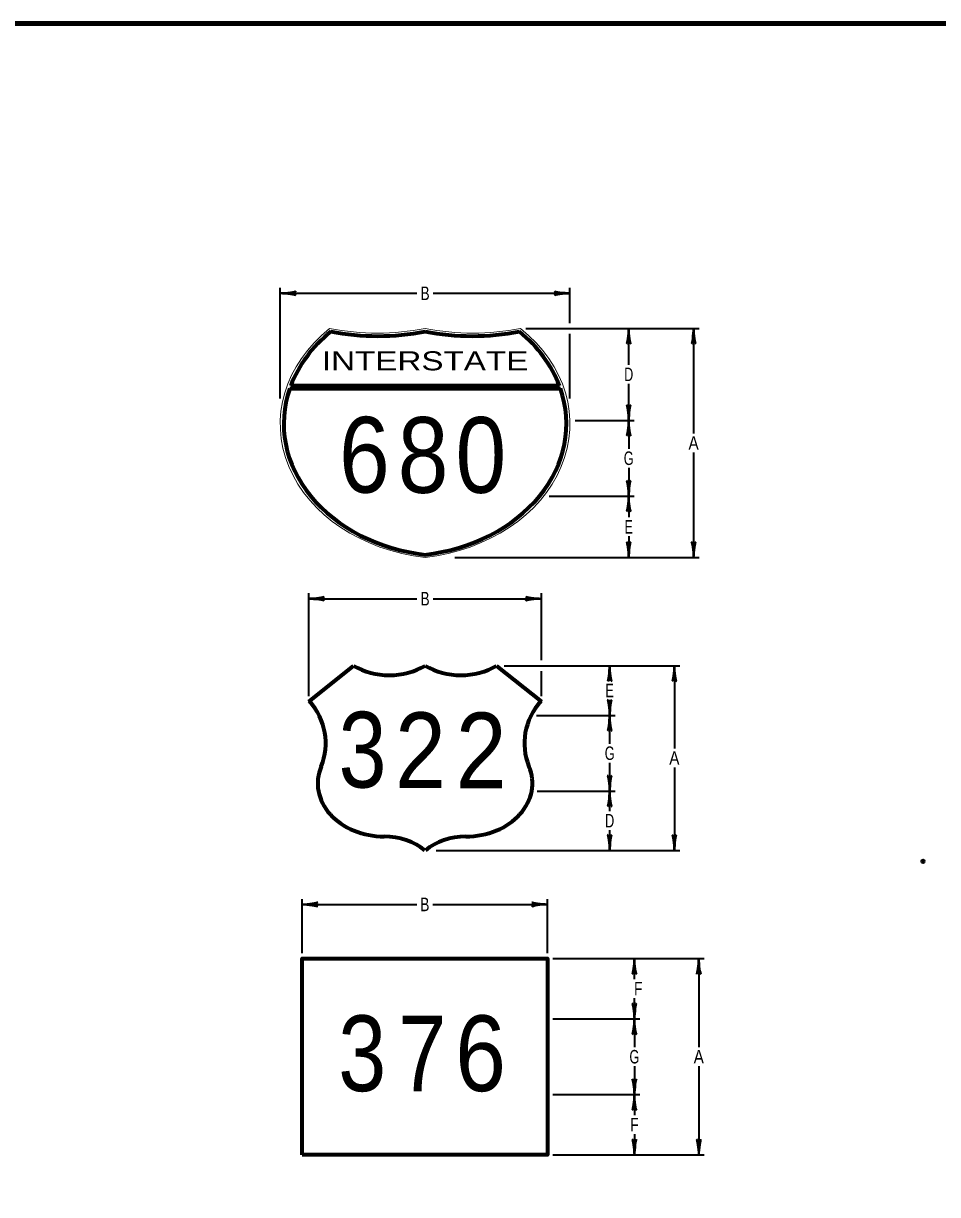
# Model space of a CAD drawing. Extents: x -96 to 760, y -448 to 96.
# Drawn here: x 135.6 to 338.4, y -170.2 to 89.7 of the extents above; entities that cross this region are included whole.
import ezdxf
from ezdxf.enums import TextEntityAlignment as Align

# ---------------------------------------------------------------- set-up
doc = ezdxf.new("R2010")
doc.units = 0
doc.header["$LTSCALE"] = 1.4
doc.header["$PDMODE"] = 32
doc.header["$PDSIZE"] = 0.7
doc.layers.add('1', color=7, linetype='Continuous', lineweight=40)

msp = doc.modelspace()

# ---------------------------------------------------------------- linework, layer by layer
at = {"layer": '1', "lineweight": 35}
for p, q in [((192.539, 6.466), (192.539, 30.981)), ((192.539, 29.781), (222.877, 29.781)), ((226.477, 29.781), (256.815, 29.781)), ((256.815, 23.192), (256.815, 30.981)), ((247.053, 21.992), (285.453, 21.992)), ((256.815, 6.466), (256.815, 20.792)), ((269.853, 13.892), (269.853, 21.992)), ((284.253, 21.992), (284.253, -1.319)), ((269.853, 1.592), (269.853, 9.692)), ((258.005, 1.592), (271.053, 1.592)), ((269.853, 1.592), (269.853, -4.708)), ((284.253, -5.519), (284.253, -28.831)), ((252.208, -15.208), (271.053, -15.208)), ((269.853, -24.119), (269.853, -28.831)), ((231.312, -28.831), (285.453, -28.831)), ((198.87, -59.569), (198.87, -36.769)), ((198.87, -37.969), (222.877, -37.969)), ((226.477, -37.969), (250.484, -37.969)), ((250.484, -51.629), (250.484, -36.769)), ((242.195, -52.829), (281.182, -52.829)), ((250.484, -59.569), (250.484, -54.029)), ((265.63, -56.239), (265.63, -52.829)), ((279.982, -52.829), (279.982, -71.215)), ((265.63, -63.849), (265.63, -60.439)), ((249.413, -63.849), (266.83, -63.849)), ((265.63, -63.849), (265.63, -70.149)), ((279.982, -75.415), (279.982, -93.801)), ((249.539, -80.649), (266.83, -80.649)), ((265.63, -89.325), (265.63, -93.801)), ((227.137, -93.801), (281.182, -93.801)), ((197.393, -116.601), (197.393, -104.601)), ((197.393, -105.799), (222.817, -105.799)), ((226.417, -105.799), (251.842, -105.799)), ((251.842, -116.599), (251.842, -104.599)), ((253.042, -117.799), (286.603, -117.799)), ((271.117, -122.389), (271.117, -117.799)), ((285.403, -117.799), (285.403, -137.479)), ((271.117, -131.179), (271.117, -126.589)), ((253.042, -131.179), (272.317, -131.179)), ((271.117, -131.179), (271.117, -137.479)), ((285.403, -141.679), (285.403, -161.359)), ((253.042, -147.979), (272.317, -147.979)), ((271.117, -156.769), (271.117, -161.359)), ((253.042, -161.359), (286.603, -161.359))]:
    msp.add_line(p, q, dxfattribs=at)
at = {"layer": '1', "lineweight": 70}
for p, q in [((194.658, 8.658), (254.696, 8.658)), ((254.469, 9.287), (194.885, 9.287)), ((198.87, -60.769), (208.795, -52.83)), ((240.559, -52.83), (250.484, -60.769))]:
    msp.add_line(p, q, dxfattribs=at)
at = {"layer": '1', "lineweight": 158}
msp.add_lwpolyline([(753.127, 89.656), (-38.573, 89.556), (-38.473, -436.444)], dxfattribs=at)
at = {"layer": '1', "lineweight": 35}
for points in [[(269.853, -8.908), (269.853, -15.208), (269.853, -19.919)], [(265.63, -74.349), (265.63, -80.649), (265.63, -85.125)], [(271.117, -141.679), (271.117, -147.979), (271.117, -152.569)]]:
    msp.add_lwpolyline(points, dxfattribs=at)
at = {"layer": '1', "lineweight": 70}
msp.add_lwpolyline([(197.393, -161.359), (197.393, -117.801), (251.842, -117.801), (251.842, -161.359)], close=True, dxfattribs=at)
at = {"layer": '1'}
for centre, major_axis, ratio, start_param, end_param in [((193.884, 29.527), (-2.108, 0.211), 0.07063, 3.1407148, 5.41811), ((193.884, 29.527), (-2.108, 0.211), 0.07063, 3.1407148, 5.41811), ((193.849, 30.112), (-2.143, -0.187), 0.122415, 0.8963533, 3.1415927), ((193.849, 30.112), (-2.143, -0.187), 0.122415, 0.8963533, 3.1415927), ((255.505, 29.449), (2.143, 0.187), 0.122415, 0.8963533, 3.1415927), ((255.505, 29.449), (2.143, 0.187), 0.122415, 0.8963533, 3.1415927), ((255.47, 30.035), (2.108, -0.211), 0.07063, 3.1407148, 5.41811), ((255.47, 30.035), (2.108, -0.211), 0.07063, 3.1407148, 5.41811), ((269.599, 20.648), (0.211, 2.108), 0.07063, 3.1407148, 5.41811), ((270.185, 20.683), (-0.187, 2.143), 0.122415, 0.8963533, 3.1415927), ((283.999, 20.648), (0.211, 2.108), 0.07063, 3.1407148, 5.41811), ((283.999, 20.648), (0.211, 2.108), 0.07063, 3.1407148, 5.41811), ((284.585, 20.683), (-0.187, 2.143), 0.122415, 0.8963533, 3.1415927), ((284.585, 20.683), (-0.187, 2.143), 0.122415, 0.8963533, 3.1415927), ((269.521, 2.902), (0.187, -2.143), 0.122415, 0.8963533, 3.1415927), ((269.521, 2.902), (0.187, -2.143), 0.122415, 0.8963533, 3.1415927), ((270.107, 2.937), (-0.211, -2.108), 0.07063, 3.1407148, 5.41811), ((270.107, 2.937), (-0.211, -2.108), 0.07063, 3.1407148, 5.41811), ((269.599, 0.248), (0.211, 2.108), 0.07063, 3.1407148, 5.41811), ((269.599, 0.248), (0.211, 2.108), 0.07063, 3.1407148, 5.41811), ((270.185, 0.283), (-0.187, 2.143), 0.122415, 0.8963533, 3.1415927), ((270.185, 0.283), (-0.187, 2.143), 0.122415, 0.8963533, 3.1415927), ((269.521, -13.898), (0.187, -2.143), 0.122415, 0.8963533, 3.1415927), ((269.521, -13.898), (0.187, -2.143), 0.122415, 0.8963533, 3.1415927), ((270.107, -13.863), (-0.211, -2.108), 0.07063, 3.1407148, 5.41811), ((270.107, -13.863), (-0.211, -2.108), 0.07063, 3.1407148, 5.41811), ((269.599, -16.552), (0.211, 2.108), 0.07063, 3.1407148, 5.41811), ((269.599, -16.552), (0.211, 2.108), 0.07063, 3.1407148, 5.41811), ((270.185, -16.517), (-0.187, 2.143), 0.122415, 0.8963533, 3.1415927), ((270.185, -16.517), (-0.187, 2.143), 0.122415, 0.8963533, 3.1415927), ((269.521, -27.522), (0.187, -2.143), 0.122415, 0.8963533, 3.1415927), ((269.521, -27.522), (0.187, -2.143), 0.122415, 0.8963533, 3.1415927), ((270.107, -27.487), (-0.211, -2.108), 0.07063, 3.1407148, 5.41811), ((270.107, -27.487), (-0.211, -2.108), 0.07063, 3.1407148, 5.41811), ((283.921, -27.522), (0.187, -2.143), 0.122415, 0.8963533, 3.1415927), ((283.921, -27.522), (0.187, -2.143), 0.122415, 0.8963533, 3.1415927), ((284.507, -27.487), (-0.211, -2.108), 0.07063, 3.1407148, 5.41811), ((284.507, -27.487), (-0.211, -2.108), 0.07063, 3.1407148, 5.41811), ((200.215, -38.223), (-2.108, 0.211), 0.07063, 3.1407148, 5.41811), ((200.215, -38.223), (-2.108, 0.211), 0.07063, 3.1407148, 5.41811), ((200.18, -37.637), (-2.143, -0.187), 0.122415, 0.8963533, 3.1415927), ((200.18, -37.637), (-2.143, -0.187), 0.122415, 0.8963533, 3.1415927), ((249.174, -38.3), (2.143, 0.187), 0.122415, 0.8963533, 3.1415927), ((249.174, -38.3), (2.143, 0.187), 0.122415, 0.8963533, 3.1415927), ((249.139, -37.715), (2.108, -0.211), 0.07063, 3.1407148, 5.41811), ((249.139, -37.715), (2.108, -0.211), 0.07063, 3.1407148, 5.41811), ((265.376, -54.173), (0.211, 2.108), 0.07063, 3.1407148, 5.41811), ((265.376, -54.173), (0.211, 2.108), 0.07063, 3.1407148, 5.41811), ((265.962, -54.138), (-0.187, 2.143), 0.122415, 0.8963533, 3.1415927), ((265.962, -54.138), (-0.187, 2.143), 0.122415, 0.8963533, 3.1415927), ((279.728, -54.173), (0.211, 2.108), 0.07063, 3.1407148, 5.41811), ((279.728, -54.173), (0.211, 2.108), 0.07063, 3.1407148, 5.41811), ((280.314, -54.138), (-0.187, 2.143), 0.122415, 0.8963533, 3.1415927), ((280.314, -54.138), (-0.187, 2.143), 0.122415, 0.8963533, 3.1415927), ((265.299, -62.539), (0.187, -2.143), 0.122415, 0.8963533, 3.1415927), ((265.299, -62.539), (0.187, -2.143), 0.122415, 0.8963533, 3.1415927), ((265.884, -62.504), (-0.211, -2.108), 0.07063, 3.1407148, 5.41811), ((265.884, -62.504), (-0.211, -2.108), 0.07063, 3.1407148, 5.41811), ((265.376, -65.193), (0.211, 2.108), 0.07063, 3.1407148, 5.41811), ((265.376, -65.193), (0.211, 2.108), 0.07063, 3.1407148, 5.41811), ((265.962, -65.158), (-0.187, 2.143), 0.122415, 0.8963533, 3.1415927), ((265.962, -65.158), (-0.187, 2.143), 0.122415, 0.8963533, 3.1415927), ((265.299, -79.339), (0.187, -2.143), 0.122415, 0.8963533, 3.1415927), ((265.299, -79.339), (0.187, -2.143), 0.122415, 0.8963533, 3.1415927), ((265.884, -79.304), (-0.211, -2.108), 0.07063, 3.1407148, 5.41811), ((265.884, -79.304), (-0.211, -2.108), 0.07063, 3.1407148, 5.41811), ((265.376, -81.993), (0.211, 2.108), 0.07063, 3.1407148, 5.41811), ((265.376, -81.993), (0.211, 2.108), 0.07063, 3.1407148, 5.41811), ((265.962, -81.958), (-0.187, 2.143), 0.122415, 0.8963533, 3.1415927), ((265.962, -81.958), (-0.187, 2.143), 0.122415, 0.8963533, 3.1415927), ((265.299, -92.491), (0.187, -2.143), 0.122415, 0.8963533, 3.1415927), ((265.884, -92.456), (-0.211, -2.108), 0.07063, 3.1407148, 5.41811), ((279.651, -92.491), (0.187, -2.143), 0.122415, 0.8963533, 3.1415927), ((279.651, -92.491), (0.187, -2.143), 0.122415, 0.8963533, 3.1415927), ((280.236, -92.456), (-0.211, -2.108), 0.07063, 3.1407148, 5.41811), ((280.236, -92.456), (-0.211, -2.108), 0.07063, 3.1407148, 5.41811), ((198.737, -106.053), (-2.108, 0.211), 0.07063, 3.1407148, 5.41811), ((198.737, -106.053), (-2.108, 0.211), 0.07063, 3.1407148, 5.41811), ((198.702, -105.468), (-2.143, -0.187), 0.122415, 0.8963533, 3.1415927), ((198.702, -105.468), (-2.143, -0.187), 0.122415, 0.8963533, 3.1415927), ((250.532, -106.131), (2.143, 0.187), 0.122415, 0.8963533, 3.1415927), ((250.532, -106.131), (2.143, 0.187), 0.122415, 0.8963533, 3.1415927), ((250.497, -105.545), (2.108, -0.211), 0.07063, 3.1407148, 5.41811), ((250.497, -105.545), (2.108, -0.211), 0.07063, 3.1407148, 5.41811), ((270.863, -119.144), (0.211, 2.108), 0.07063, 3.1407148, 5.41811), ((270.863, -119.144), (0.211, 2.108), 0.07063, 3.1407148, 5.41811), ((271.449, -119.109), (-0.187, 2.143), 0.122415, 0.8963533, 3.1415927), ((271.449, -119.109), (-0.187, 2.143), 0.122415, 0.8963533, 3.1415927), ((285.149, -119.144), (0.211, 2.108), 0.07063, 3.1407148, 5.41811), ((285.149, -119.144), (0.211, 2.108), 0.07063, 3.1407148, 5.41811), ((285.734, -119.109), (-0.187, 2.143), 0.122415, 0.8963533, 3.1415927), ((285.734, -119.109), (-0.187, 2.143), 0.122415, 0.8963533, 3.1415927), ((270.786, -129.87), (0.187, -2.143), 0.122415, 0.8963533, 3.1415927), ((270.786, -129.87), (0.187, -2.143), 0.122415, 0.8963533, 3.1415927), ((271.371, -129.835), (-0.211, -2.108), 0.07063, 3.1407148, 5.41811), ((271.371, -129.835), (-0.211, -2.108), 0.07063, 3.1407148, 5.41811), ((270.863, -132.524), (0.211, 2.108), 0.07063, 3.1407148, 5.41811), ((270.863, -132.524), (0.211, 2.108), 0.07063, 3.1407148, 5.41811), ((271.449, -132.489), (-0.187, 2.143), 0.122415, 0.8963533, 3.1415927), ((271.449, -132.489), (-0.187, 2.143), 0.122415, 0.8963533, 3.1415927), ((270.786, -146.67), (0.187, -2.143), 0.122415, 0.8963533, 3.1415927), ((270.786, -146.67), (0.187, -2.143), 0.122415, 0.8963533, 3.1415927), ((271.371, -146.635), (-0.211, -2.108), 0.07063, 3.1407148, 5.41811), ((271.371, -146.635), (-0.211, -2.108), 0.07063, 3.1407148, 5.41811), ((270.863, -149.324), (0.211, 2.108), 0.07063, 3.1407148, 5.41811), ((270.863, -149.324), (0.211, 2.108), 0.07063, 3.1407148, 5.41811), ((271.449, -149.289), (-0.187, 2.143), 0.122415, 0.8963533, 3.1415927), ((271.449, -149.289), (-0.187, 2.143), 0.122415, 0.8963533, 3.1415927), ((270.786, -160.05), (0.187, -2.143), 0.122415, 0.8963533, 3.1415927), ((270.786, -160.05), (0.187, -2.143), 0.122415, 0.8963533, 3.1415927), ((271.371, -160.015), (-0.211, -2.108), 0.07063, 3.1407148, 5.41811), ((271.371, -160.015), (-0.211, -2.108), 0.07063, 3.1407148, 5.41811), ((285.071, -160.05), (0.187, -2.143), 0.122415, 0.8963533, 3.1415927), ((285.071, -160.05), (0.187, -2.143), 0.122415, 0.8963533, 3.1415927), ((285.657, -160.015), (-0.211, -2.108), 0.07063, 3.1407148, 5.41811), ((285.657, -160.015), (-0.211, -2.108), 0.07063, 3.1407148, 5.41811)]:
    msp.add_ellipse(centre, major_axis=major_axis, ratio=ratio, start_param=start_param, end_param=end_param, dxfattribs=at)
at = {"layer": '1', "lineweight": 13}
for centre, major_axis, start_param, end_param in [((229.971, 0.816), (-37.434, 0), 5.4977871, 7.7120846), ((214.089, 55.345), (43.014, 0), 4.463679, 4.961099), ((235.265, 55.345), (43.014, 0), 4.463679, 4.961099), ((219.383, 0.816), (-37.434, 0), 1.7126934, 3.9269908)]:
    msp.add_ellipse(centre, major_axis=major_axis, ratio=0.8, start_param=start_param, end_param=end_param, dxfattribs=at)
at = {"layer": '1', "lineweight": 70}
for centre, major_axis, start_param, end_param in [((229.971, 0.816), (-36.648, 0), 5.5098712, 5.9900965), ((214.089, 55.345), (43.8, 0), 4.4739857, 4.9565425), ((235.265, 55.345), (43.8, 0), 4.4682355, 4.9507923), ((219.383, 0.816), (-36.648, 0), 3.4346814, 3.9149068), ((229.971, 0.816), (-36.648, 0), 6.0124299, 7.7120846), ((219.383, 0.816), (-36.648, 0), 1.7126934, 3.4123481), ((216.736, -44.358), (13.237, 0), 4.0689907, 5.3557872), ((232.618, -44.358), (13.237, 0), 4.0689908, 5.3557873), ((182.067, -70.034), (20.581, 0), 5.9660402, 6.8866281), ((267.287, -70.034), (20.581, 0), 2.5381499, 3.4587377), ((215.603, -78.922), (14.747, 0), 2.8178694, 4.7123069), ((233.751, -78.922), (14.747, 0), 4.7124711, 6.6069086), ((215.602, -100.699), (-12.476, 0), 3.9047808, 4.712389), ((233.752, -100.699), (-12.476, 0), 4.712389, 5.5199972)]:
    msp.add_ellipse(centre, major_axis=major_axis, ratio=0.8, start_param=start_param, end_param=end_param, dxfattribs=at)
at = {"layer": '1'}
msp.add_point((335.156, -96.227), dxfattribs=at)

# ---------------------------------------------------------------- texts
for s, height, width, p in [('B', 3, 0.75, (224.677, 28.281)), ('INTERSTATE', 4.235, 1.3, (224.677, 12.681)), ('D', 3, 0.7, (269.853, 10.292)), ('A', 3, 0.85, (284.253, -4.919)), ('G', 3, 0.7, (269.853, -8.308)), ('E', 3, 0.7, (269.853, -23.519)), ('B', 3, 0.75, (224.677, -39.469)), ('E', 3, 0.7, (265.63, -59.839)), ('G', 3, 0.7, (265.63, -73.749)), ('A', 3, 0.85, (279.982, -74.815)), ('D', 3, 0.7, (265.63, -88.725)), ('B', 3, 0.75, (224.617, -107.299)), ('F', 3, 0.75, (271.972, -125.979)), ('G', 3, 0.7, (271.117, -141.079)), ('A', 3, 0.85, (285.403, -141.079)), ('F', 3, 0.75, (271.117, -156.169))]:
    msp.add_text(s, height=height, dxfattribs=dict(at, width=width)).set_placement(p, align=Align.CENTER)
for s, width, p in [('6', 0.9, (205.588, -14.433)), ('8', 0.9, (218.613, -14.484)), ('0', 0.9, (231.434, -14.484)), ('3', 0.85, (205.487, -79.864)), ('2', 0.9, (218.034, -80.003)), ('2', 0.9, (231.505, -80.049)), ('3', 0.85, (205.418, -147.219)), ('7', 0.85, (218.745, -147.283)), ('6', 0.9, (231.37, -147.219))]:
    msp.add_text(s, height=16.8, dxfattribs=dict(at, width=width)).set_placement(p)

doc.saveas('drawing.dxf')
